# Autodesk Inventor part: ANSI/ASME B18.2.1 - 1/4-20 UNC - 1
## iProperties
Comments: To add or edit properties for Autodesk Inventor files, use iProperties.
Created: 2004-12
Part Number: ANSI/ASME B18.2.1 - 1/4-20 UNC - 1
Vendor: Autodesk Inc.
Document SubType Name: Modeling
Designer: John Blackburn
Material: Default
Description: Hex Bolt - UNC (Regular Thread - Inch)
Standard: ANSI/ASME B18.2.1
Alert: To add or edit properties for Autodesk Inventor files, use iProperties.
Control State: 0
Master: False
Checked Out: False
Shininess: 64.0
Length Units: 11272
Angle Units: 11279
Time Units: 11290
Mass Units: 11286
Length Display Precision: 3
Angle Display Precision: 2
Compacted: True
EGR: 3
Classification: un/spsc 31161513
Density: 0.0
Volumn: 0.0
Area: 0.0
PropertySet Name: Model Information
Author: John Blackburn
Revision Number: 8
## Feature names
1. Body [Revolution]
2. Head [Extrusion]
3. Chamfer1 [Revolution]
4. Chamfer2
